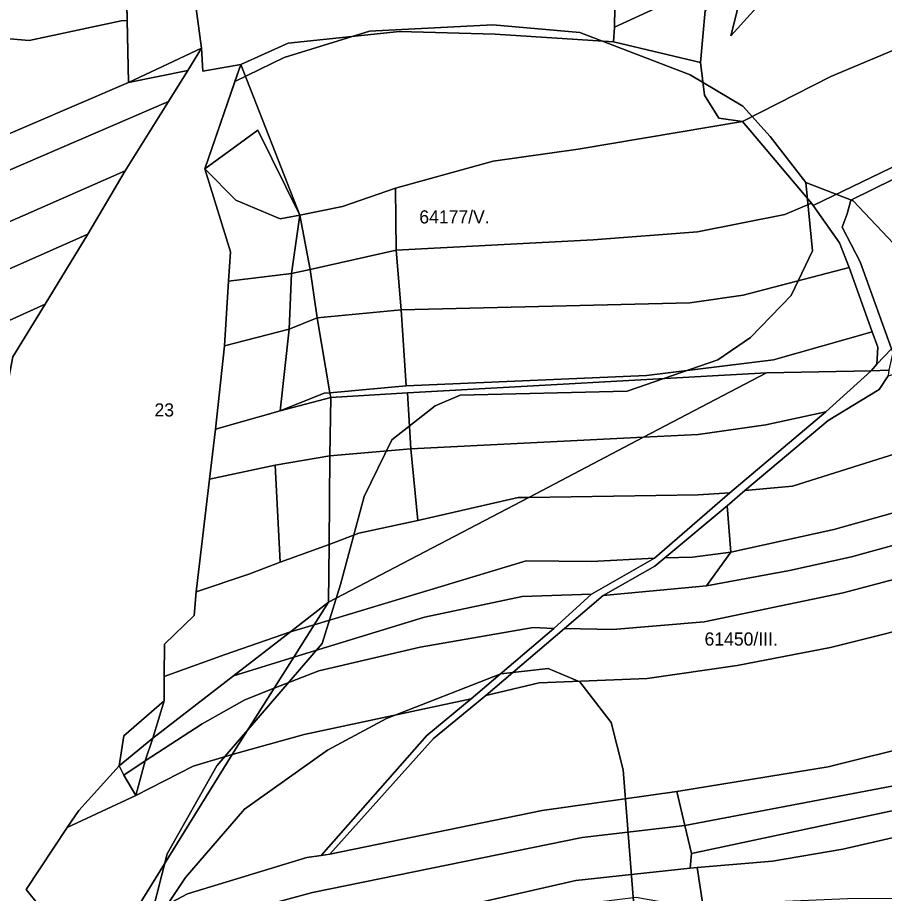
# Model space of a CAD drawing. Extents: x -521261 to -517465, y -1182764 to -1179456.
# Drawn here: x -520563.9 to -520234.1, y -1181487.6 to -1181154.3 of the extents above; entities that cross this region are included whole.
import ezdxf

# ---------------------------------------------------------------- set-up
doc = ezdxf.new("R2010")
doc.units = 0
for name, color, linetype in [('95560013', 7, 'Continuous'), ('95610013', 7, 'Continuous'), ('95620013', 7, 'Continuous'), ('95640013', 7, 'Continuous'), ('95660013', 7, 'Continuous')]:
    doc.layers.add(name, color=color, linetype=linetype)

msp = doc.modelspace()

# ---------------------------------------------------------------- linework, layer by layer
at = {"layer": '95560013'}
for points in [[(-520499.14, -1181174.37), (-520506.5, -1181186.19), (-520636.58, -1181242.29), (-520635.15, -1181227.75), (-520521.72, -1181178.92)], [(-520506.5, -1181186.19), (-520522.96, -1181212.61), (-520638.68, -1181263.52), (-520636.58, -1181242.29)], [(-520522.96, -1181212.61), (-520537.12, -1181236.65), (-520640.57, -1181282.52), (-520638.68, -1181263.52)], [(-520537.12, -1181236.65), (-520553.33, -1181263.31), (-520642.68, -1181303.81), (-520640.57, -1181282.52)], [(-520553.33, -1181263.31), (-520565.67, -1181283.42), (-520567.22, -1181291.34), (-520644.91, -1181326.28), (-520642.68, -1181303.81)]]:
    msp.add_lwpolyline(points, close=True, dxfattribs=at)
at = {"layer": '95610013'}
for points in [[(-520501.61, -1181108.38), (-520522.92, -1181119.2), (-520521.72, -1181178.92), (-520635.15, -1181227.75), (-520634.86, -1181222.95), (-520634.84, -1181222.55), (-520632.77, -1181200.01), (-520629.67, -1181169.79), (-520626.5, -1181138.86), (-520614.85, -1181131.39), (-520585.05, -1181120.87), (-520571.69, -1181120.15), (-520556.17, -1181117.12), (-520527.54, -1181106.61)], [(-520492.59, -1181211.81), (-520478.96, -1181172.1), (-520456.42, -1181229.43), (-520472.47, -1181197.08)], [(-520452.55, -1181250.11), (-520459.68, -1181251.69), (-520456.42, -1181229.43)], [(-520459.68, -1181251.69), (-520452.55, -1181250.11), (-520449.84, -1181268.49), (-520460.48, -1181272.82)], [(-520460.48, -1181272.82), (-520449.84, -1181268.49), (-520445.1, -1181297.08), (-520447.21, -1181297.17), (-520463.92, -1181303.97)], [(-520176.89, -1181287.4), (-520178.71, -1181305.72), (-520202.19, -1181311.58), (-520269.09, -1181332.61), (-520287.18, -1181334.21), (-520255.53, -1181307.58), (-520236.03, -1181295.81), (-520232.63, -1181290.61), (-520225.08, -1181288.33)], [(-520232.39, -1181288.47), (-520232.63, -1181290.61), (-520236.03, -1181295.81), (-520255.53, -1181307.58), (-520287.18, -1181334.21), (-520293.89, -1181340.02), (-520317.68, -1181359.9), (-520321.39, -1181363.01), (-520341.1, -1181374.15), (-520355.78, -1181386.73), (-520385.73, -1181412.26), (-520405.58, -1181428.65), (-520445.12, -1181472.67), (-520448.41, -1181473.09), (-520408.16, -1181427.45), (-520391.32, -1181413.46), (-520359.89, -1181386.72), (-520345.57, -1181373.71), (-520321.57, -1181359.96), (-520292.94, -1181335.11), (-520256.36, -1181304.34), (-520239.14, -1181288.67)], [(-520239.14, -1181288.67), (-520256.36, -1181304.34), (-520279.13, -1181309.22), (-520304.9, -1181312.94), (-520325.73, -1181313.98), (-520278.96, -1181289.49)], [(-520447.21, -1181297.17), (-520445.1, -1181297.08), (-520444.74, -1181298.79), (-520463.92, -1181303.97)], [(-520256.36, -1181304.34), (-520292.94, -1181335.11), (-520304.9, -1181335.94), (-520369.41, -1181336.85), (-520325.73, -1181313.98), (-520304.9, -1181312.94), (-520279.13, -1181309.22)], [(-520202.19, -1181311.58), (-520178.71, -1181305.72), (-520181.27, -1181328.86), (-520253.27, -1181349.13), (-520292.48, -1181357.65), (-520293.89, -1181340.02), (-520287.18, -1181334.21), (-520269.09, -1181332.61)], [(-520182.58, -1181342.83), (-520195.46, -1181345.45), (-520246.59, -1181359.49), (-520270.2, -1181364.68), (-520301.73, -1181370.53), (-520292.48, -1181357.65), (-520253.27, -1181349.13), (-520181.27, -1181328.86)], [(-520304.9, -1181335.94), (-520292.94, -1181335.11), (-520321.57, -1181359.96), (-520345.48, -1181361.23), (-520370.38, -1181361.05), (-520450.98, -1181385.32), (-520445.56, -1181376.73), (-520369.41, -1181336.85)], [(-520293.89, -1181340.02), (-520292.48, -1181357.65), (-520307.11, -1181359.56), (-520317.68, -1181359.9)], [(-520195.46, -1181345.45), (-520182.58, -1181342.83), (-520184.06, -1181356.65), (-520191.33, -1181357.73), (-520249.83, -1181373.13), (-520302.68, -1181384.22), (-520337.44, -1181387.17), (-520355.78, -1181386.73), (-520341.1, -1181374.15), (-520301.73, -1181370.53), (-520270.2, -1181364.68), (-520246.59, -1181359.49)], [(-520191.33, -1181357.73), (-520184.06, -1181356.65), (-520186.19, -1181379.03), (-520211.1, -1181383.08), (-520254.64, -1181394.05), (-520290.16, -1181400.78), (-520324.33, -1181405.78), (-520365.37, -1181407.48), (-520385.73, -1181412.26), (-520355.78, -1181386.73), (-520337.44, -1181387.17), (-520302.68, -1181384.22), (-520249.83, -1181373.13)], [(-520321.57, -1181359.96), (-520345.57, -1181373.71), (-520371.95, -1181374.6), (-520409.08, -1181382.45), (-520458.79, -1181397.7), (-520450.98, -1181385.32), (-520370.38, -1181361.05), (-520345.48, -1181361.23)], [(-520292.48, -1181357.65), (-520301.73, -1181370.53), (-520341.1, -1181374.15), (-520321.39, -1181363.01), (-520317.68, -1181359.9), (-520307.11, -1181359.56)], [(-520345.57, -1181373.71), (-520359.89, -1181386.72), (-520367.66, -1181386.35), (-520410.73, -1181393.88), (-520449.21, -1181402.93), (-520466.24, -1181409.51), (-520458.79, -1181397.7), (-520409.08, -1181382.45), (-520371.95, -1181374.6)], [(-520211.1, -1181383.08), (-520201.65, -1181426.98), (-520219.86, -1181430.55), (-520255.51, -1181439.46), (-520313.09, -1181448.84), (-520364.32, -1181456), (-520445.12, -1181472.67), (-520405.58, -1181428.65), (-520385.73, -1181412.26), (-520365.37, -1181407.48), (-520324.33, -1181405.78), (-520290.16, -1181400.78), (-520254.64, -1181394.05)], [(-520367.66, -1181386.35), (-520359.89, -1181386.72), (-520391.32, -1181413.46), (-520454.87, -1181427.08), (-520482.21, -1181434.76), (-520466.24, -1181409.51), (-520449.21, -1181402.93), (-520410.73, -1181393.88)], [(-520454.87, -1181427.08), (-520391.32, -1181413.46), (-520408.16, -1181427.45), (-520448.41, -1181473.09), (-520453.82, -1181473.89), (-520499.28, -1181487.67), (-520522.86, -1181500.26), (-520482.21, -1181434.76)], [(-520219.86, -1181430.55), (-520201.65, -1181426.98), (-520210.56, -1181442.77), (-520310.06, -1181461.77), (-520313.09, -1181448.84), (-520255.51, -1181439.46)], [(-520216.32, -1181452.99), (-520307.52, -1181472.34), (-520310.06, -1181461.77), (-520210.56, -1181442.77)], [(-520364.32, -1181456), (-520313.09, -1181448.84), (-520310.06, -1181461.77), (-520349.03, -1181466.33), (-520451.71, -1181487.19), (-520499.12, -1181500), (-520532.26, -1181515.4), (-520522.86, -1181500.26), (-520499.28, -1181487.67), (-520453.82, -1181473.89), (-520448.41, -1181473.09), (-520445.12, -1181472.67)], [(-520310.06, -1181461.77), (-520307.52, -1181472.34), (-520307.98, -1181477.97), (-520351.52, -1181482.6), (-520431.47, -1181500.94), (-520459.61, -1181504.33), (-520494.99, -1181514.51), (-520526.22, -1181522.02), (-520532.26, -1181515.4), (-520499.12, -1181500), (-520451.71, -1181487.19), (-520349.03, -1181466.33)], [(-520305.37, -1181477.77), (-520303.01, -1181492.71), (-520307.36, -1181492.97), (-520328.5, -1181489.14), (-520351.25, -1181491.92), (-520373.3, -1181496.48), (-520409.22, -1181505.26), (-520429.99, -1181510.25), (-520445.11, -1181514.18), (-520460.28, -1181517.71), (-520491.73, -1181522.23), (-520524.43, -1181529), (-520526.22, -1181522.02), (-520494.99, -1181514.51), (-520459.61, -1181504.33), (-520431.47, -1181500.94), (-520351.52, -1181482.6), (-520307.98, -1181477.97)]]:
    msp.add_lwpolyline(points, close=True, dxfattribs=at)
at = {"layer": '95620013'}
for points in [[(-520522.92, -1181119.2), (-520501.61, -1181108.38), (-520493.92, -1181165.95), (-520521.72, -1181178.92)], [(-520493.92, -1181165.95), (-520499.14, -1181174.37), (-520521.72, -1181178.92)], [(-520492.59, -1181211.81), (-520472.47, -1181197.08), (-520456.42, -1181229.43), (-520463.99, -1181230.83), (-520480.86, -1181223.76)], [(-520492.59, -1181211.81), (-520480.86, -1181223.76), (-520463.99, -1181230.83), (-520456.42, -1181229.43), (-520459.68, -1181251.69), (-520483.68, -1181254.59), (-520482.87, -1181243.46)], [(-520459.68, -1181251.69), (-520460.48, -1181272.82), (-520485.2, -1181279.13), (-520483.68, -1181254.59)], [(-520463.92, -1181303.97), (-520444.74, -1181298.79), (-520445.05, -1181321.08), (-520465.91, -1181324.54), (-520490.82, -1181329.91), (-520488.58, -1181310.87)], [(-520465.91, -1181324.54), (-520445.05, -1181321.08), (-520445.28, -1181354.75), (-520463.97, -1181361.55)], [(-520490.82, -1181329.91), (-520465.91, -1181324.54), (-520463.97, -1181361.55), (-520475.85, -1181366.08), (-520495.9, -1181372.75)], [(-520463.97, -1181361.55), (-520445.28, -1181354.75), (-520445.56, -1181376.73), (-520460.08, -1181388.06), (-520484.89, -1181396.7), (-520508.07, -1181405.08), (-520508.01, -1181392.69), (-520496.62, -1181381.76), (-520495.9, -1181372.75), (-520475.85, -1181366.08)], [(-520460.08, -1181388.06), (-520481.69, -1181404.72), (-520512.46, -1181428.48), (-520508.13, -1181414.32), (-520508.07, -1181405.08), (-520484.89, -1181396.7)], [(-520147.36, -1181438.44), (-520153.14, -1181441.18), (-520214.82, -1181457.85), (-520220.56, -1181464.03), (-520249.84, -1181470.67), (-520276.65, -1181475.26), (-520305.37, -1181477.77), (-520307.98, -1181477.97), (-520307.52, -1181472.34), (-520216.32, -1181452.99)], [(-520220.56, -1181464.03), (-520188.68, -1181456.43), (-520183.26, -1181487.11), (-520201.97, -1181488.21), (-520211.67, -1181488.9), (-520222.29, -1181489.55), (-520248.06, -1181489.62), (-520277.86, -1181490.96), (-520303.01, -1181492.71), (-520305.37, -1181477.77), (-520276.65, -1181475.26), (-520249.84, -1181470.67)]]:
    msp.add_lwpolyline(points, close=True, dxfattribs=at)
msp.add_lwpolyline([(-520565.67, -1181283.42), (-520553.33, -1181263.31), (-520537.12, -1181236.65), (-520522.96, -1181212.61), (-520506.5, -1181186.19), (-520499.14, -1181174.37), (-520493.92, -1181165.95), (-520493.39, -1181174.7), (-520478.96, -1181172.1), (-520492.59, -1181211.81), (-520482.87, -1181243.46), (-520483.68, -1181254.59), (-520485.2, -1181279.13), (-520488.58, -1181310.87), (-520490.82, -1181329.91), (-520495.9, -1181372.75), (-520496.62, -1181381.76), (-520508.01, -1181392.69), (-520508.07, -1181405.08), (-520508.13, -1181414.32), (-520523.42, -1181427.65), (-520525.16, -1181439.01), (-520540.59, -1181455.99), (-520545.05, -1181462.49), (-520560.55, -1181486.11), (-520551.17, -1181497.81)], dxfattribs=at)
at = {"layer": '95640013'}
for points in [[(-520277.6, -1181032.76), (-520253.94, -1181048.36), (-520239.97, -1181052.18), (-520220.57, -1181049.61), (-520214.23, -1181077.46), (-520289.13, -1181105.34), (-520281.95, -1181113.37), (-520272.96, -1181130.65), (-520279.13, -1181132.17), (-520305.16, -1181142.6), (-520319.71, -1181150.12), (-520336.76, -1181157.91), (-520335.2, -1181068.61), (-520331.46, -1181067.2), (-520328.37, -1181062.33), (-520315.05, -1181055.77), (-520311.25, -1181044.99), (-520301.71, -1181034.37), (-520284.69, -1181029.91)], [(-520335.2, -1181068.61), (-520336.76, -1181157.91), (-520337.13, -1181163.47), (-520382.21, -1181160.56), (-520418.54, -1181159.62), (-520460.89, -1181164.03), (-520478.96, -1181172.1), (-520493.39, -1181174.7), (-520493.92, -1181165.95), (-520501.61, -1181108.38), (-520422.02, -1181070.48), (-520405.61, -1181073.38), (-520391.51, -1181071.12), (-520368.56, -1181074.46), (-520357.23, -1181067.33)], [(-520208.33, -1181106.65), (-520202.7, -1181126.58), (-520208.38, -1181133.79), (-520200.46, -1181154.03), (-520254.49, -1181176.66), (-520288.03, -1181193.76), (-520297.05, -1181192.49), (-520302.49, -1181183.79), (-520304.08, -1181171.38), (-520302.27, -1181151.64), (-520287.43, -1181140.94), (-520292.51, -1181161.26), (-520277.55, -1181144.55), (-520279.13, -1181132.17), (-520272.96, -1181130.65), (-520243.42, -1181116.34), (-520210.11, -1181097.99)], [(-520098.46, -1181133.43), (-520161.15, -1181169.69), (-520183.49, -1181188.27), (-520261.22, -1181225.79), (-520261.82, -1181224.94), (-520288.03, -1181193.76), (-520254.49, -1181176.66), (-520200.46, -1181154.03), (-520189.15, -1181149.27), (-520084.62, -1181113.41)], [(-520305.16, -1181142.6), (-520279.13, -1181132.17), (-520277.55, -1181144.55), (-520292.51, -1181161.26), (-520287.43, -1181140.94), (-520302.27, -1181151.64), (-520304.08, -1181171.38), (-520337.13, -1181163.47), (-520336.76, -1181157.91), (-520319.71, -1181150.12)], [(-520109.27, -1181144.59), (-520159.71, -1181173.72), (-520173.94, -1181187.85), (-520246.91, -1181223.77), (-520248.19, -1181228.92), (-520250.09, -1181234), (-520243.27, -1181247.26), (-520231.33, -1181280.35), (-520236.97, -1181286.19), (-520236.52, -1181279.68), (-520238.76, -1181273.9), (-520247.52, -1181249.42), (-520251.17, -1181239.95), (-520261.22, -1181225.79), (-520183.49, -1181188.27), (-520161.15, -1181169.69), (-520098.46, -1181133.43)], [(-520159.71, -1181173.72), (-520109.27, -1181144.59), (-520231.33, -1181280.35), (-520243.27, -1181247.26), (-520250.09, -1181234), (-520248.19, -1181228.92), (-520246.91, -1181223.77), (-520173.94, -1181187.85)], [(-520382.21, -1181160.56), (-520337.13, -1181163.47), (-520304.08, -1181171.38), (-520302.49, -1181183.79), (-520297.05, -1181192.49), (-520288.03, -1181193.76), (-520350.61, -1181204.32), (-520382.91, -1181208.96), (-520420.08, -1181219.13), (-520440.2, -1181226.19), (-520456.42, -1181229.43), (-520478.96, -1181172.1), (-520460.89, -1181164.03), (-520418.54, -1181159.62)], [(-520288.03, -1181193.76), (-520261.82, -1181224.94), (-520272.02, -1181229.17), (-520305.14, -1181235.78), (-520344.85, -1181238.88), (-520419.8, -1181242.73), (-520420.08, -1181219.13), (-520382.91, -1181208.96), (-520350.61, -1181204.32)], [(-520420.08, -1181219.13), (-520419.8, -1181242.73), (-520452.55, -1181250.11), (-520456.42, -1181229.43), (-520440.2, -1181226.19)], [(-520261.22, -1181225.79), (-520251.17, -1181239.95), (-520247.52, -1181249.42), (-520287.82, -1181259.93), (-520308.06, -1181262.87), (-520417.95, -1181265.45), (-520419.8, -1181242.73), (-520344.85, -1181238.88), (-520305.14, -1181235.78), (-520272.02, -1181229.17), (-520261.82, -1181224.94)], [(-520452.55, -1181250.11), (-520419.8, -1181242.73), (-520417.95, -1181265.45), (-520449.84, -1181268.49)], [(-520247.52, -1181249.42), (-520238.76, -1181273.9), (-520276.25, -1181284.54), (-520324.6, -1181290.45), (-520415.98, -1181294.38), (-520417.95, -1181265.45), (-520308.06, -1181262.87), (-520287.82, -1181259.93)], [(-520449.84, -1181268.49), (-520417.95, -1181265.45), (-520415.98, -1181294.38), (-520445.1, -1181297.08)], [(-520485.2, -1181279.13), (-520460.48, -1181272.82), (-520463.92, -1181303.97), (-520488.58, -1181310.87)], [(-520238.76, -1181273.9), (-520236.52, -1181279.68), (-520236.97, -1181286.19), (-520239.14, -1181288.67), (-520278.96, -1181289.49), (-520415.55, -1181297.12), (-520444.74, -1181298.79), (-520445.1, -1181297.08), (-520415.98, -1181294.38), (-520324.6, -1181290.45), (-520276.25, -1181284.54)], [(-520230.87, -1181281.73), (-520232.39, -1181288.47), (-520239.14, -1181288.67), (-520236.97, -1181286.19), (-520231.33, -1181280.35)], [(-520415.55, -1181297.12), (-520278.96, -1181289.49), (-520325.73, -1181313.98), (-520414.2, -1181318.37)], [(-520444.74, -1181298.79), (-520415.55, -1181297.12), (-520414.2, -1181318.37), (-520445.05, -1181321.08)], [(-520325.73, -1181313.98), (-520369.41, -1181336.85), (-520373.4, -1181336.91), (-520411.57, -1181345.69), (-520414.2, -1181318.37)], [(-520445.05, -1181321.08), (-520414.2, -1181318.37), (-520411.57, -1181345.69), (-520434.09, -1181350.49), (-520445.28, -1181354.75)], [(-520373.4, -1181336.91), (-520369.41, -1181336.85), (-520445.56, -1181376.73), (-520445.28, -1181354.75), (-520434.09, -1181350.49), (-520411.57, -1181345.69)], [(-520450.98, -1181385.32), (-520460.08, -1181388.06), (-520445.56, -1181376.73)], [(-520460.08, -1181388.06), (-520450.98, -1181385.32), (-520458.79, -1181397.7), (-520481.69, -1181404.72)], [(-520458.79, -1181397.7), (-520466.24, -1181409.51), (-520477.44, -1181413.84), (-520493.61, -1181423.04), (-520515.29, -1181437.12), (-520512.46, -1181428.48), (-520481.69, -1181404.72)], [(-520477.44, -1181413.84), (-520466.24, -1181409.51), (-520482.21, -1181434.76), (-520497.08, -1181439.12), (-520518.89, -1181450.27), (-520515.29, -1181437.12), (-520493.61, -1181423.04)], [(-520523.42, -1181427.65), (-520508.13, -1181414.32), (-520512.46, -1181428.48), (-520525.16, -1181439.01)], [(-520512.46, -1181428.48), (-520515.29, -1181437.12), (-520523.38, -1181442.55), (-520525.16, -1181439.01)], [(-520497.08, -1181439.12), (-520482.21, -1181434.76), (-520522.86, -1181500.26), (-520538.34, -1181508.53), (-520551.17, -1181497.81), (-520560.55, -1181486.11), (-520545.05, -1181462.49), (-520518.89, -1181450.27)], [(-520523.38, -1181442.55), (-520515.29, -1181437.12), (-520518.89, -1181450.27)], [(-520523.38, -1181442.55), (-520518.89, -1181450.27), (-520545.05, -1181462.49), (-520540.59, -1181455.99), (-520525.16, -1181439.01)]]:
    msp.add_lwpolyline(points, close=True, dxfattribs=at)
at = {"layer": '95660013'}
for points in [[(-520501.61, -1181108.38), (-520493.92, -1181165.95), (-520493.39, -1181174.7), (-520478.96, -1181172.1), (-520481.18, -1181178.57), (-520492.59, -1181211.81), (-520472.47, -1181197.08), (-520456.42, -1181229.43), (-520459.68, -1181251.69), (-520460.48, -1181272.82), (-520485.2, -1181279.13), (-520488.58, -1181310.87), (-520463.92, -1181303.97), (-520444.74, -1181298.79), (-520445.05, -1181321.08), (-520445.28, -1181354.75), (-520445.56, -1181376.73), (-520460.08, -1181388.06), (-520481.69, -1181404.72), (-520512.46, -1181428.48), (-520508.13, -1181414.32), (-520523.42, -1181427.65), (-520525.16, -1181439.01), (-520540.59, -1181455.99), (-520545.05, -1181462.49), (-520560.55, -1181486.11), (-520551.17, -1181497.81)], [(-520211, -1181261), (-520246, -1181224), (-520264, -1181217), (-520277.5, -1181199.5), (-520288, -1181188), (-520308, -1181176), (-520350, -1181160), (-520383, -1181157), (-520430, -1181159.5), (-520462.5, -1181169.5), (-520481.18, -1181178.57), (-520478.96, -1181172.1), (-520493.39, -1181174.7), (-520493.92, -1181165.95), (-520501.61, -1181108.38)], [(-520522.92, -1181119.2), (-520522.19, -1181155.36), (-520524.5, -1181155.5), (-520559.5, -1181163), (-520616.5, -1181158), (-520628.5, -1181158.39), (-520626.5, -1181138.86)], [(-520568.81, -1181488.5), (-520571.45, -1181464.53), (-520574.24, -1181438.77), (-520576.08, -1181410.39), (-520577.99, -1181383.26), (-520578.73, -1181355.74), (-520578.82, -1181343.7), (-520574.59, -1181324.96), (-520567.22, -1181291.34), (-520565.67, -1181283.42), (-520553.33, -1181263.31), (-520537.12, -1181236.65), (-520522.96, -1181212.61), (-520506.5, -1181186.19), (-520499.14, -1181174.37), (-520521.72, -1181178.92), (-520522.19, -1181155.36), (-520522.92, -1181119.2)], [(-520616.5, -1181158), (-520559.5, -1181163), (-520524.5, -1181155.5), (-520522.19, -1181155.36), (-520521.72, -1181178.92), (-520499.14, -1181174.37), (-520506.5, -1181186.19), (-520522.96, -1181212.61), (-520537.12, -1181236.65), (-520553.33, -1181263.31), (-520565.67, -1181283.42)], [(-520551.17, -1181497.81), (-520560.55, -1181486.11), (-520545.05, -1181462.49), (-520540.59, -1181455.99), (-520525.16, -1181439.01), (-520523.42, -1181427.65), (-520508.13, -1181414.32), (-520512.46, -1181428.48), (-520481.69, -1181404.72), (-520460.08, -1181388.06), (-520445.56, -1181376.73), (-520445.28, -1181354.75), (-520445.05, -1181321.08), (-520444.74, -1181298.79), (-520463.92, -1181303.97), (-520488.58, -1181310.87), (-520485.2, -1181279.13), (-520460.48, -1181272.82), (-520459.68, -1181251.69), (-520456.42, -1181229.43), (-520472.47, -1181197.08), (-520492.59, -1181211.81), (-520481.18, -1181178.57), (-520462.5, -1181169.5), (-520430, -1181159.5), (-520383, -1181157), (-520350, -1181160), (-520308, -1181176), (-520288, -1181188), (-520277.5, -1181199.5), (-520264, -1181217), (-520261.5, -1181243), (-520269.5, -1181260), (-520285, -1181276), (-520297.5, -1181284.5), (-520332, -1181296.5), (-520395.5, -1181298), (-520405, -1181302), (-520421.5, -1181315), (-520432, -1181336.5), (-520441, -1181370), (-520448, -1181392.5), (-520488, -1181439), (-520507, -1181472.5), (-520515, -1181504)], [(-520328.5, -1181503.5), (-520333.5, -1181440.5), (-520338, -1181422.5), (-520350, -1181407), (-520362, -1181402), (-520380, -1181404), (-520423.5, -1181421), (-520446, -1181433), (-520477.5, -1181455.5), (-520500, -1181481.5), (-520515, -1181504), (-520507, -1181472.5), (-520488, -1181439), (-520448, -1181392.5), (-520441, -1181370), (-520432, -1181336.5), (-520421.5, -1181315), (-520405, -1181302), (-520395.5, -1181298), (-520332, -1181296.5), (-520297.5, -1181284.5), (-520285, -1181276), (-520269.5, -1181260), (-520261.5, -1181243), (-520264, -1181217), (-520246, -1181224), (-520211, -1181261)], [(-520515, -1181504), (-520500, -1181481.5), (-520477.5, -1181455.5), (-520446, -1181433), (-520423.5, -1181421), (-520380, -1181404), (-520362, -1181402), (-520350, -1181407), (-520338, -1181422.5), (-520333.5, -1181440.5), (-520328.5, -1181503.5)], [(-520303.01, -1181492.71), (-520305.37, -1181477.77), (-520307.98, -1181477.97), (-520307.52, -1181472.34), (-520216.32, -1181452.99)], [(-520216.32, -1181452.99), (-520307.52, -1181472.34), (-520307.98, -1181477.97), (-520305.37, -1181477.77), (-520303.01, -1181492.71)]]:
    msp.add_lwpolyline(points, dxfattribs=at)

# ---------------------------------------------------------------- texts
for s, rotation, p in [('64177/V.', 360, (-520411.03, -1181232.62)), ('23', 360, (-520511.78, -1181306.08)), ('61450/III.', 0, (-520302.51, -1181393.25))]:
    msp.add_text(s, height=5, rotation=rotation, dxfattribs=at).set_placement(p)

doc.saveas('drawing.dxf')
